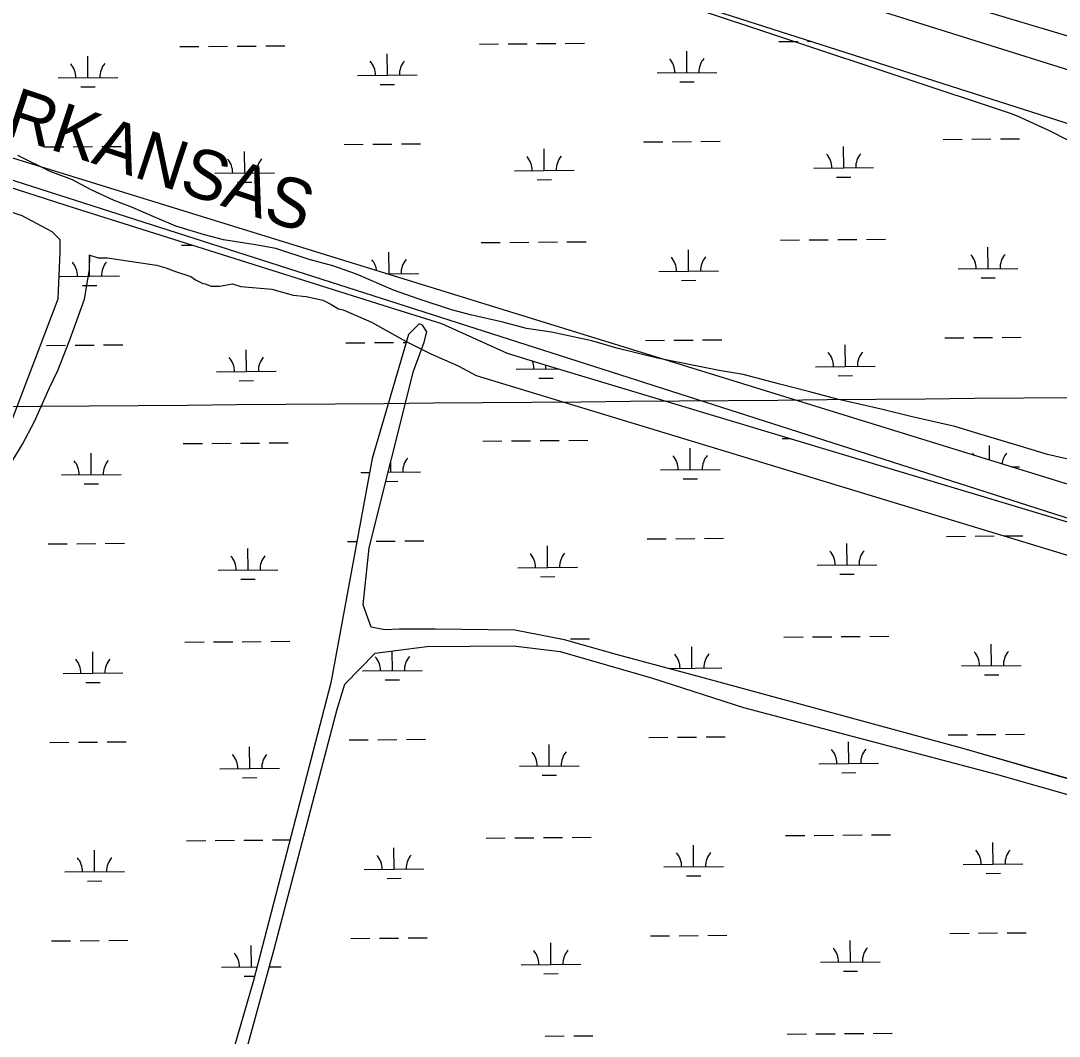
# Model space of a CAD drawing. Extents: x 3568792 to 3606828, y 529143 to 554785.
# Drawn here: x 3589468 to 3591208, y 539689 to 541391 of the extents above; entities that cross this region are included whole.
import ezdxf

# ---------------------------------------------------------------- set-up
doc = ezdxf.new("R2010")
doc.units = 0
for name, color, linetype in [('V-GRID-MAJR', 7, 'Continuous'), ('V-RAIL-IDEN', 7, 'Continuous'), ('V-RAIL-TRAK', 7, 'Continuous'), ('V-ROAD-CNTR', 7, 'Continuous'), ('V-SITE-VEGE', 7, 'Continuous'), ('V-TOPO-SHOR', 7, 'Continuous'), ('V-WETL-SWMP', 7, 'Continuous')]:
    doc.layers.add(name, color=color, linetype=linetype)

msp = doc.modelspace()

# ---------------------------------------------------------------- linework, layer by layer
at = {"layer": 'V-GRID-MAJR'}
msp.add_spline([(3571033, 540592.1), (3576309.2, 540634.7), (3581585.4, 540678.1), (3586861.7, 540722.2), (3592137.9, 540767.1), (3597414.1, 540812.8), (3602690.3, 540859.2)], degree=3, dxfattribs=at)
at = {"layer": 'V-RAIL-TRAK'}
msp.add_lwpolyline([(3588701.9, 541364.3), (3595635.2, 539144), (3598756.4, 538211.6)], dxfattribs=at)
at = {"layer": 'V-ROAD-CNTR'}
msp.add_lwpolyline([(3590287.8, 541602.3), (3591975.1, 541072.5), (3593264.5, 540671.4), (3594324.9, 540335.1), (3595195.6, 540063.3), (3596054.3, 539794.4), (3596991.5, 539499.1), (3598079.9, 539159.1), (3598141.1, 539139.6), (3599140, 538813.5), (3599951.1, 538576.7)], dxfattribs=at)
at = {"layer": 'V-SITE-VEGE'}
for p, q in [((3589583.2, 540973.8), (3589583.4, 540997.7)), ((3589583.4, 540997.7), (3589597.3, 540993.6)), ((3589597.3, 540993.6), (3589613.3, 540993.5)), ((3589613.3, 540993.5), (3589695.1, 540980.8)), ((3589574.7, 540923.9), (3589583.2, 540973.8)), ((3589695.1, 540980.8), (3589711, 540976.6)), ((3589711, 540976.6), (3589727, 540970.5)), ((3589727, 540970.5), (3589752.9, 540962.2)), ((3589752.9, 540962.2), (3589760.8, 540956.2)), ((3589760.8, 540956.2), (3589772.7, 540950.1)), ((3589772.7, 540950.1), (3589776.7, 540950)), ((3589776.7, 540950), (3589786.7, 540946)), ((3589786.7, 540946), (3589800.6, 540945.8)), ((3589800.6, 540945.8), (3589822.7, 540949.6)), ((3589822.7, 540949.6), (3589836.6, 540945.5)), ((3589836.6, 540945.5), (3589888.5, 540941)), ((3589888.5, 540941), (3589924.4, 540930.7)), ((3589564.5, 540896), (3589574.7, 540923.9)), ((3589924.4, 540930.7), (3589946.3, 540928.5)), ((3589946.3, 540928.5), (3589974.2, 540922.3)), ((3589974.2, 540922.3), (3589986.1, 540916.2)), ((3589986.1, 540916.2), (3590000.1, 540908.1)), ((3590000.1, 540908.1), (3590008, 540906)), ((3590008, 540906), (3590055.8, 540885.6)), ((3589550.1, 540856.2), (3589564.5, 540896)), ((3590055.8, 540885.6), (3590113.4, 540853.1)), ((3589529.7, 540804.5), (3589550.1, 540856.2)), ((3590113.4, 540853.1), (3590155.2, 540832.7)), ((3590155.2, 540832.7), (3590200.9, 540812.4)), ((3589515.4, 540774.6), (3589529.7, 540804.5)), ((3590200.9, 540812.4), (3590230.7, 540796.1)), ((3590230.7, 540796.1), (3591906, 540287.5)), ((3589491, 540718.9), (3589515.4, 540774.6)), ((3589470.7, 540681.2), (3589491, 540718.9)), ((3589438.2, 540627.5), (3589470.7, 540681.2))]:
    msp.add_line(p, q, dxfattribs=at)
for points in [[(3590576, 541418.2), (3591127.6, 541235.4), (3591137.6, 541231.3), (3591191.3, 541206.8), (3591254.9, 541174.3)], [(3591252.1, 540649), (3591188.3, 540663.6), (3591142.5, 540678), (3591078.8, 540696.5), (3591033, 540710.9), (3590959.2, 540727.6), (3590909.4, 540740), (3590835.6, 540756.7), (3590787.8, 540769.1), (3590740, 540781.5), (3590678.2, 540798), (3590638.3, 540804.4), (3590576.5, 540816.9), (3590534.6, 540825.3), (3590466.9, 540841.9), (3590425, 540854.3), (3590357.3, 540868.9), (3590315.4, 540875.2), (3590275.5, 540885.6), (3590221.7, 540898.1), (3590189.8, 540906.3), (3590134, 540924.8), (3590092.2, 540939.2), (3590030.5, 540965.7), (3589990.7, 540980.1), (3589950.9, 540990.4), (3589895.1, 541008.9), (3589861.2, 541015.2), (3589807.3, 541023.7), (3589775.5, 541032), (3589727.7, 541046.4), (3589693.8, 541060.7), (3589652, 541079), (3589624.2, 541089.3), (3589584.4, 541107.6), (3589554.6, 541123.9), (3589516.8, 541138.2), (3589463.1, 541164.6)]]:
    msp.add_lwpolyline(points, dxfattribs=at)
at = {"layer": 'V-TOPO-SHOR'}
for p, q in [((3590135.3, 540883), (3590117.4, 540864.7)), ((3590141.2, 540880.4), (3590135.3, 540883)), ((3590148.5, 540869.6), (3590141.2, 540880.4)), ((3590143.9, 540852.1), (3590148.5, 540869.6)), ((3590117.4, 540864.7), (3590056.6, 540657)), ((3590125.7, 540803.4), (3590143.9, 540852.1)), ((3590051.4, 540507.3), (3590125.7, 540803.4)), ((3590056.6, 540657), (3589987.3, 540281)), ((3590041.4, 540411.7), (3590051.4, 540507.3)), ((3590055.2, 540374.2), (3590041.4, 540411.7)), ((3590077.7, 540370), (3590055.2, 540374.2)), ((3590102, 540371.2), (3590077.7, 540370)), ((3590162.1, 540370.9), (3590102, 540371.2)), ((3590295.9, 540369.5), (3590162.1, 540370.9)), ((3590378.7, 540353.3), (3590295.9, 540369.5)), ((3590467.5, 540328.1), (3590378.7, 540353.3)), ((3590011, 540279.1), (3590061.4, 540331.1)), ((3590061.4, 540331.1), (3590148.5, 540341.9)), ((3590148.5, 540341.9), (3590293.3, 540343.2)), ((3590293.3, 540343.2), (3590371.5, 540333.8)), ((3590371.5, 540333.8), (3590526.5, 540288.7)), ((3590613.5, 540289), (3590467.5, 540328.1)), ((3589987.3, 540281), (3589857.8, 539782.5)), ((3589998, 540237.2), (3590011, 540279.1)), ((3590526.5, 540288.7), (3590679, 540239.9)), ((3591048.7, 540170.3), (3590613.5, 540289)), ((3590679, 540239.9), (3591102.2, 540128.2)), ((3589892.7, 539834.7), (3589998, 540237.2)), ((3591714, 539978.8), (3591048.7, 540170.3)), ((3591102.2, 540128.2), (3591702.7, 539957.1)), ((3589818.7, 539565.7), (3589892.7, 539834.7)), ((3589857.8, 539782.5), (3589758.5, 539439.3))]:
    msp.add_line(p, q, dxfattribs=at)
msp.add_lwpolyline([(3588388, 542258.1), (3590797.4, 541492.7), (3591794.5, 541194.6), (3591855.9, 541181.5), (3591849.2, 541167.8), (3591876.7, 541147.6), (3591904, 541141), (3591931, 541161.7), (3592136, 541088.5), (3592539.1, 540955.6), (3593044.6, 540796.4)], dxfattribs=at)
at = {"layer": 'V-WETL-SWMP'}
for p, q in [((3590738.2, 541355.7), (3590770.2, 541356)), ((3590786.2, 541356.1), (3590793.2, 541356.2)), ((3589734.4, 541347.3), (3589766.4, 541347.5)), ((3589782.4, 541347.7), (3589814.4, 541347.9)), ((3589830.4, 541348.1), (3589862.4, 541348.3)), ((3589878.4, 541348.5), (3589910.4, 541348.7)), ((3590236.3, 541351.5), (3590268.3, 541351.8)), ((3590284.3, 541351.9), (3590316.3, 541352.2)), ((3590332.3, 541352.3), (3590364.3, 541352.6)), ((3590380.3, 541352.7), (3590412.3, 541353)), ((3590584, 541303.7), (3590583.7, 541339.7)), ((3589580.3, 541295.2), (3589579.9, 541331.2)), ((3590082.1, 541299.4), (3590081.8, 541335.4)), ((3590534, 541303.3), (3590634, 541304.1)), ((3589530.3, 541294.8), (3589630.3, 541295.6)), ((3590032.1, 541299), (3590132.1, 541299.9)), ((3590070.3, 541283.9), (3590094.3, 541284.1)), ((3590572.2, 541288.2), (3590596.2, 541288.4)), ((3589568.4, 541279.7), (3589592.4, 541279.9)), ((3589025.7, 541247.6), (3589557.4, 541077.1)), ((3589470.4, 541063.7), (3589062.5, 541197.5)), ((3589555.8, 541179.6), (3589587.8, 541179.8)), ((3589603.8, 541180), (3589635.8, 541180.2)), ((3590009.7, 541183.4), (3590041.7, 541183.7)), ((3590057.7, 541183.8), (3590089.7, 541184.1)), ((3590105.7, 541184.2), (3590137.7, 541184.5)), ((3590511.6, 541187.6), (3590543.6, 541187.9)), ((3590559.6, 541188), (3590591.6, 541188.3)), ((3590607.6, 541188.4), (3590639.6, 541188.7)), ((3590846.8, 541144), (3590846.5, 541180)), ((3591013.5, 541191.9), (3591045.5, 541192.1)), ((3591061.5, 541192.3), (3591093.5, 541192.5)), ((3591109.5, 541192.7), (3591141.5, 541192.9)), ((3589507.8, 541179.2), (3589539.8, 541179.4)), ((3589843, 541135.6), (3589842.7, 541171.6)), ((3590344.9, 541139.8), (3590344.6, 541175.8)), ((3589793, 541135.1), (3589893, 541136)), ((3590294.9, 541139.4), (3590394.9, 541140.2)), ((3590796.8, 541143.6), (3590896.8, 541144.5)), ((3590835, 541128.5), (3590859, 541128.7)), ((3589831.2, 541120), (3589855.2, 541120.2)), ((3590333.1, 541124.3), (3590357.1, 541124.5)), ((3589557.4, 541077.1), (3590085, 540910.8)), ((3589520.6, 541036.9), (3589470.4, 541063.7)), ((3589534, 541023.6), (3589520.6, 541036.9)), ((3589534, 541003.5), (3589534, 541023.6)), ((3590741, 541023.1), (3590773, 541023.3)), ((3590789, 541023.5), (3590821, 541023.7)), ((3590837, 541023.9), (3590869, 541024.1)), ((3590885, 541024.3), (3590917, 541024.5)), ((3589737.3, 541014.6), (3589755.1, 541014.8)), ((3590239.1, 541018.8), (3590271.1, 541019.1)), ((3590287.1, 541019.2), (3590319.1, 541019.5)), ((3590335.1, 541019.6), (3590367.1, 541019.9)), ((3590383.1, 541020), (3590415.1, 541020.3)), ((3590586.8, 540971), (3590586.5, 541007)), ((3591088.7, 540975.3), (3591088.4, 541011.3)), ((3589530.6, 540924.5), (3589534, 541003.5)), ((3589583.1, 540962.6), (3589582.8, 540998.6)), ((3590084.9, 540966.8), (3590084.6, 541002.8)), ((3590536.8, 540970.6), (3590636.8, 540971.4)), ((3591038.7, 540974.8), (3591138.7, 540975.7)), ((3589533.1, 540962.1), (3589633.1, 540963)), ((3590079.7, 540966.7), (3590134.9, 540967.2)), ((3590575, 540955.5), (3590599, 540955.7)), ((3591076.9, 540959.7), (3591100.9, 540959.9)), ((3589571.2, 540947), (3589595.2, 540947.2)), ((3589057.8, 539688.9), (3589530.6, 540924.5)), ((3590085, 540910.8), (3590172.7, 540883.1)), ((3590135.3, 540883), (3590117.4, 540864.7)), ((3590141.2, 540880.4), (3590135.3, 540883)), ((3590148.5, 540869.6), (3590141.2, 540880.4)), ((3590143.9, 540852.1), (3590148.5, 540869.6)), ((3590172.7, 540883.1), (3590283, 540833.5)), ((3590012.6, 540850.8), (3590044.6, 540851)), ((3590117.4, 540864.7), (3590056.6, 540657)), ((3590060.6, 540851.2), (3590092.6, 540851.4)), ((3590108.6, 540851.6), (3590113.5, 540851.6)), ((3590125.7, 540803.4), (3590143.9, 540852.1)), ((3590514.4, 540855), (3590546.4, 540855.2)), ((3590562.4, 540855.4), (3590594.4, 540855.6)), ((3590610.4, 540855.8), (3590642.4, 540856.1)), ((3591016.3, 540859.2), (3591048.3, 540859.5)), ((3591064.3, 540859.6), (3591096.3, 540859.9)), ((3591112.3, 540860), (3591144.3, 540860.3)), ((3589510.7, 540846.5), (3589542.7, 540846.8)), ((3589558.7, 540846.9), (3589590.7, 540847.2)), ((3589606.7, 540847.3), (3589638.7, 540847.6)), ((3589845.9, 540802.9), (3589845.6, 540838.9)), ((3590283, 540833.5), (3590344.4, 540814.7)), ((3590849.6, 540811.4), (3590849.3, 540847.4)), ((3590344.4, 540814.7), (3591759.7, 540388.7)), ((3589795.9, 540802.5), (3589895.9, 540803.3)), ((3590051.4, 540507.3), (3590125.7, 540803.4)), ((3590297.8, 540806.7), (3590368.8, 540807.3)), ((3590347.8, 540807.2), (3590347.7, 540813.7)), ((3590799.6, 540810.9), (3590899.6, 540811.8)), ((3589834, 540787.4), (3589858, 540787.6)), ((3590335.9, 540791.6), (3590359.9, 540791.8)), ((3590837.8, 540795.8), (3590861.8, 540796)), ((3589740.1, 540682), (3589772.1, 540682.2)), ((3589788.1, 540682.4), (3589820.1, 540682.6)), ((3589836.1, 540682.8), (3589868.1, 540683)), ((3589884.1, 540683.2), (3589916.1, 540683.4)), ((3590242, 540686.2), (3590274, 540686.5)), ((3590290, 540686.6), (3590322, 540686.9)), ((3590338, 540687), (3590370, 540687.3)), ((3590386, 540687.4), (3590418, 540687.7)), ((3590743.8, 540690.4), (3590756.9, 540690.5)), ((3591091.4, 540654.2), (3591091.2, 540678.6)), ((3589585.9, 540629.9), (3589585.6, 540665.9)), ((3590589.7, 540638.4), (3590589.4, 540674.4)), ((3590056.6, 540657), (3589987.3, 540281)), ((3590087.8, 540634.1), (3590087.7, 540651.9)), ((3591128, 540642.9), (3591141.5, 540643)), ((3589535.9, 540629.5), (3589635.9, 540630.3)), ((3590037.8, 540633.7), (3590052.3, 540633.8)), ((3590083.2, 540634.1), (3590137.8, 540634.6)), ((3590539.7, 540638), (3590639.7, 540638.8)), ((3590577.8, 540622.8), (3590601.8, 540623)), ((3589574, 540614.4), (3589598, 540614.6)), ((3590079.3, 540618.6), (3590099.9, 540618.8)), ((3590015.4, 540518.1), (3590031, 540518.2)), ((3590063.4, 540518.5), (3590095.4, 540518.8)), ((3590111.4, 540518.9), (3590143.4, 540519.2)), ((3590517.3, 540522.3), (3590549.3, 540522.6)), ((3590565.3, 540522.7), (3590597.3, 540523)), ((3590613.3, 540523.1), (3590645.3, 540523.4)), ((3591019.1, 540526.6), (3591051.1, 540526.8)), ((3591067.1, 540527), (3591099.1, 540527.2)), ((3591115.1, 540527.4), (3591147.1, 540527.6)), ((3589513.5, 540513.9), (3589545.5, 540514.1)), ((3589561.5, 540514.3), (3589593.5, 540514.5)), ((3589609.5, 540514.7), (3589641.5, 540514.9)), ((3589848.7, 540470.3), (3589848.4, 540506.3)), ((3590041.4, 540411.7), (3590051.4, 540507.3)), ((3590350.6, 540474.5), (3590350.3, 540510.5)), ((3590852.5, 540478.7), (3590852.2, 540514.7)), ((3589798.7, 540469.8), (3589898.7, 540470.7)), ((3590300.6, 540474.1), (3590400.6, 540474.9)), ((3590802.5, 540478.3), (3590902.5, 540479.1)), ((3589836.8, 540454.7), (3589860.8, 540454.9)), ((3590338.7, 540459), (3590362.7, 540459.2)), ((3590840.6, 540463.2), (3590864.6, 540463.4)), ((3590055.2, 540374.2), (3590041.4, 540411.7)), ((3590077.7, 540370), (3590055.2, 540374.2)), ((3590102, 540371.2), (3590077.7, 540370)), ((3590162.1, 540370.9), (3590102, 540371.2)), ((3590295.9, 540369.5), (3590162.1, 540370.9)), ((3590378.7, 540353.3), (3590295.9, 540369.5)), ((3589742.9, 540349.3), (3589774.9, 540349.6)), ((3589790.9, 540349.7), (3589822.9, 540350)), ((3589838.9, 540350.1), (3589870.9, 540350.4)), ((3589886.9, 540350.5), (3589918.9, 540350.8)), ((3590372.2, 540354.6), (3590372.8, 540354.6)), ((3590467.5, 540328.1), (3590378.7, 540353.3)), ((3590388.8, 540354.7), (3590420.8, 540355)), ((3590746.7, 540357.8), (3590778.7, 540358)), ((3590794.7, 540358.2), (3590826.7, 540358.4)), ((3590842.7, 540358.6), (3590874.6, 540358.8)), ((3590890.6, 540359), (3590922.6, 540359.2)), ((3591094.4, 540309.9), (3591094.1, 540345.9)), ((3589588.7, 540297.2), (3589588.4, 540333.2)), ((3590011, 540279.1), (3590061.4, 540331.1)), ((3590061.4, 540331.1), (3590148.5, 540341.9)), ((3590090.6, 540301.5), (3590090.3, 540334.7)), ((3590148.5, 540341.9), (3590293.3, 540343.2)), ((3590293.3, 540343.2), (3590371.5, 540333.8)), ((3590371.5, 540333.8), (3590526.5, 540288.7)), ((3590613.5, 540289), (3590467.5, 540328.1)), ((3590592.5, 540305.7), (3590592.2, 540341.7)), ((3591044.4, 540309.5), (3591144.4, 540310.4)), ((3589538.7, 540296.8), (3589638.7, 540297.7)), ((3590040.6, 540301.1), (3590140.6, 540301.9)), ((3590552.4, 540305.4), (3590642.5, 540306.1)), ((3591082.5, 540294.4), (3591106.5, 540294.6)), ((3589576.8, 540281.7), (3589600.8, 540281.9)), ((3589987.3, 540281), (3589857.8, 539782.5)), ((3589998, 540237.2), (3590011, 540279.1)), ((3590078.7, 540285.9), (3590102.7, 540286.1)), ((3590526.5, 540288.7), (3590679, 540239.9)), ((3591048.7, 540170.3), (3590613.5, 540289)), ((3590679, 540239.9), (3591102.2, 540128.2)), ((3589892.7, 539834.7), (3589998, 540237.2)), ((3590520.1, 540189.7), (3590552.1, 540189.9)), ((3590568.1, 540190.1), (3590600.1, 540190.3)), ((3590616.1, 540190.5), (3590648.1, 540190.7)), ((3591022, 540193.9), (3591054, 540194.2)), ((3591070, 540194.3), (3591102, 540194.6)), ((3591118, 540194.7), (3591150, 540195)), ((3589516.3, 540181.2), (3589548.3, 540181.5)), ((3589564.3, 540181.6), (3589596.3, 540181.9)), ((3589612.3, 540182), (3589644.3, 540182.3)), ((3589851.5, 540137.6), (3589851.2, 540173.6)), ((3590018.2, 540185.4), (3590050.2, 540185.7)), ((3590066.2, 540185.8), (3590098.2, 540186.1)), ((3590114.2, 540186.2), (3590146.2, 540186.5)), ((3590353.4, 540141.8), (3590353.1, 540177.8)), ((3590855.3, 540146.1), (3590855, 540182.1)), ((3591703.1, 539982.8), (3591048.7, 540170.3)), ((3589801.5, 540137.2), (3589901.5, 540138)), ((3590303.4, 540141.4), (3590403.4, 540142.2)), ((3590805.3, 540145.6), (3590905.3, 540146.5)), ((3589839.6, 540122.1), (3589863.6, 540122.3)), ((3590341.5, 540126.3), (3590365.5, 540126.5)), ((3590843.4, 540130.5), (3590867.4, 540130.7)), ((3591102.2, 540128.2), (3591702.7, 539957.1)), ((3589745.7, 540016.6), (3589777.7, 540016.9)), ((3589793.7, 540017), (3589825.7, 540017.3)), ((3589841.7, 540017.4), (3589873.7, 540017.7)), ((3589889.7, 540017.8), (3589919, 540018.1)), ((3590247.6, 540020.9), (3590279.6, 540021.1)), ((3590295.6, 540021.3), (3590327.6, 540021.5)), ((3590343.6, 540021.7), (3590375.6, 540021.9)), ((3590391.6, 540022.1), (3590423.6, 540022.3)), ((3590749.5, 540025.1), (3590781.5, 540025.4)), ((3590797.5, 540025.5), (3590829.5, 540025.8)), ((3590845.5, 540025.9), (3590877.5, 540026.2)), ((3590893.5, 540026.3), (3590925.5, 540026.6)), ((3589591.5, 539964.6), (3589591.2, 540000.6)), ((3590093.4, 539968.8), (3590093.1, 540004.8)), ((3590595.3, 539973), (3590595, 540009)), ((3591097.2, 539977.3), (3591096.9, 540013.3)), ((3589541.5, 539964.2), (3589641.5, 539965)), ((3590043.4, 539968.4), (3590143.4, 539969.2)), ((3590545.3, 539972.6), (3590645.3, 539973.5)), ((3591047.2, 539976.9), (3591147.2, 539977.7)), ((3591085.3, 539961.8), (3591109.3, 539962)), ((3589579.7, 539949), (3589603.7, 539949.3)), ((3590081.5, 539953.3), (3590105.5, 539953.5)), ((3590583.4, 539957.5), (3590607.4, 539957.7)), ((3590522.9, 539857), (3590554.9, 539857.3)), ((3590570.9, 539857.4), (3590602.9, 539857.7)), ((3590618.9, 539857.8), (3590650.9, 539858.1)), ((3591024.8, 539861.2), (3591056.8, 539861.5)), ((3591072.8, 539861.6), (3591104.8, 539861.9)), ((3591120.8, 539862), (3591152.8, 539862.3)), ((3589519.1, 539848.5), (3589551.1, 539848.8)), ((3589567.1, 539848.9), (3589599.1, 539849.2)), ((3589615.1, 539849.3), (3589647.1, 539849.6)), ((3589854.3, 539804.9), (3589854, 539840.9)), ((3590021, 539852.8), (3590053, 539853)), ((3590069, 539853.2), (3590101, 539853.4)), ((3590117, 539853.6), (3590149, 539853.8)), ((3590356.2, 539809.2), (3590355.9, 539845.2)), ((3590858.1, 539813.4), (3590857.8, 539849.4)), ((3589818.7, 539565.7), (3589892.7, 539834.7)), ((3589804.3, 539804.5), (3589863.7, 539805)), ((3589884.6, 539805.2), (3589904.3, 539805.4)), ((3590306.2, 539808.7), (3590406.2, 539809.6)), ((3590808.1, 539813), (3590908.1, 539813.8)), ((3589842.4, 539789.4), (3589859.7, 539789.5)), ((3590344.3, 539793.6), (3590368.3, 539793.8)), ((3590846.2, 539797.9), (3590870.2, 539798.1)), ((3589857.8, 539782.5), (3589758.5, 539439.3)), ((3590346.4, 539689), (3590378.4, 539689.3)), ((3590394.4, 539689.4), (3590426.4, 539689.7)), ((3590752.3, 539692.4), (3590784.3, 539692.7)), ((3590800.3, 539692.8), (3590832.3, 539693.1)), ((3590848.3, 539693.2), (3590880.3, 539693.5)), ((3590896.3, 539693.6), (3590928.3, 539693.9))]:
    msp.add_line(p, q, dxfattribs=at)
msp.add_lwpolyline([(3589155.5, 541252.3), (3589039.1, 541301.1), (3589039.1, 541317.8), (3589055.8, 541341.3), (3589102.6, 541398.1), (3589226.3, 541528.5), (3589313.3, 541615.5), (3589430.3, 541682.4), (3589453.7, 541702.4), (3589493.9, 541729.2), (3589524, 541745.9), (3589567.4, 541745.9), (3589641.2, 541724.8), (3591813.1, 541029.8), (3591813.7, 541025.5), (3591823.7, 540995.6), (3591831.4, 540961.5), (3591801.1, 540761.9), (3591778.2, 540465.7), (3591776.5, 540442.5)], close=True, dxfattribs=at)
for centre, start, end in [((3589635.5, 541296.2), 139.7115, 181.2552), ((3590026.9, 541299.5), 359.7115, 41.2552), ((3590137.4, 541300.4), 139.7115, 181.2552), ((3590528.8, 541303.7), 359.7115, 41.2552), ((3590639.3, 541304.6), 139.7115, 181.2552), ((3589525, 541295.2), 359.7115, 41.2552), ((3590289.7, 541139.8), 359.7115, 41.2552), ((3590400.2, 541140.7), 139.7115, 181.2552), ((3590791.6, 541144), 359.7115, 41.2552), ((3590902.1, 541145), 139.7115, 181.2552), ((3589787.8, 541135.6), 359.7115, 41.2552), ((3589898.3, 541136.5), 139.7115, 181.2552), ((3590029.7, 540966.8), 7.4961, 41.2552), ((3590140.2, 540967.7), 139.7115, 181.2552), ((3590531.6, 540971), 359.7115, 41.2552), ((3590642.1, 540972), 139.7115, 181.2552), ((3591033.5, 540975.3), 359.7115, 41.2552), ((3591144, 540976.2), 139.7115, 181.2552), ((3589527.9, 540962.6), 359.7115, 41.2552), ((3589638.3, 540963.5), 139.7115, 181.2552), ((3590794.4, 540811.4), 359.7115, 41.2552), ((3590904.9, 540812.3), 139.7115, 181.2552), ((3589790.7, 540802.9), 359.7115, 41.2552), ((3589901.1, 540803.9), 139.7115, 181.2552), ((3590292.5, 540807.2), 359.7115, 22.3362), ((3590403, 540808.1), 180.7629, 181.2552), ((3590143, 540635.1), 139.7115, 181.2552), ((3590534.4, 540638.4), 359.7115, 41.2552), ((3590644.9, 540639.3), 139.7115, 181.2552), ((3591036.3, 540642.6), 33.7099, 41.2552), ((3591146.8, 540643.5), 139.7115, 172.8933), ((3589530.7, 540629.9), 359.7115, 41.2552), ((3589641.1, 540630.8), 139.7115, 181.2552), ((3590797.2, 540478.7), 359.7115, 41.2552), ((3590907.7, 540479.7), 139.7115, 181.2552), ((3589793.5, 540470.3), 359.7115, 41.2552), ((3589903.9, 540471.2), 139.7115, 181.2552), ((3590295.3, 540474.5), 359.7115, 41.2552), ((3590405.8, 540475.4), 139.7115, 181.2552), ((3590537.3, 540305.7), 359.7115, 41.2552), ((3590647.7, 540306.7), 139.7115, 181.2552), ((3591039.1, 540310), 359.7115, 41.2552), ((3591149.6, 540310.9), 139.7115, 181.2552), ((3589533.5, 540297.3), 359.7115, 41.2552), ((3589644, 540298.2), 139.7115, 181.2552), ((3590035.4, 540301.5), 359.7115, 41.2552), ((3590145.8, 540302.4), 139.7115, 181.2552), ((3589796.3, 540137.6), 359.7115, 41.2552), ((3589906.7, 540138.5), 139.7115, 181.2552), ((3590298.2, 540141.8), 359.7115, 41.2552), ((3590408.6, 540142.8), 139.7115, 181.2552), ((3590800, 540146.1), 359.7115, 41.2552), ((3590910.5, 540147), 139.7115, 181.2552), ((3590540.1, 539973.1), 359.7115, 41.2552), ((3590650.5, 539974), 139.7115, 181.2552), ((3591041.9, 539977.3), 359.7115, 41.2552), ((3591152.4, 539978.2), 139.7115, 181.2552), ((3589536.3, 539964.6), 359.7115, 41.2552), ((3589646.8, 539965.5), 139.7115, 181.2552), ((3590038.2, 539968.8), 359.7115, 41.2552), ((3590148.7, 539969.8), 139.7115, 181.2552), ((3589799.1, 539804.9), 359.7115, 41.2552), ((3590301, 539809.2), 359.7115, 41.2552), ((3590411.4, 539810.1), 139.7115, 181.2552), ((3590802.9, 539813.4), 359.7115, 41.2552), ((3590913.3, 539814.3), 139.7115, 181.2552)]:
    msp.add_arc(centre, 35.2, start, end, dxfattribs=at)

# ---------------------------------------------------------------- texts
at = {"layer": 'V-RAIL-IDEN'}
msp.add_text('ARKANSAS', height=83, rotation=341.758, dxfattribs=at).set_placement((3589367.3, 541224.4))

doc.saveas('drawing.dxf')
